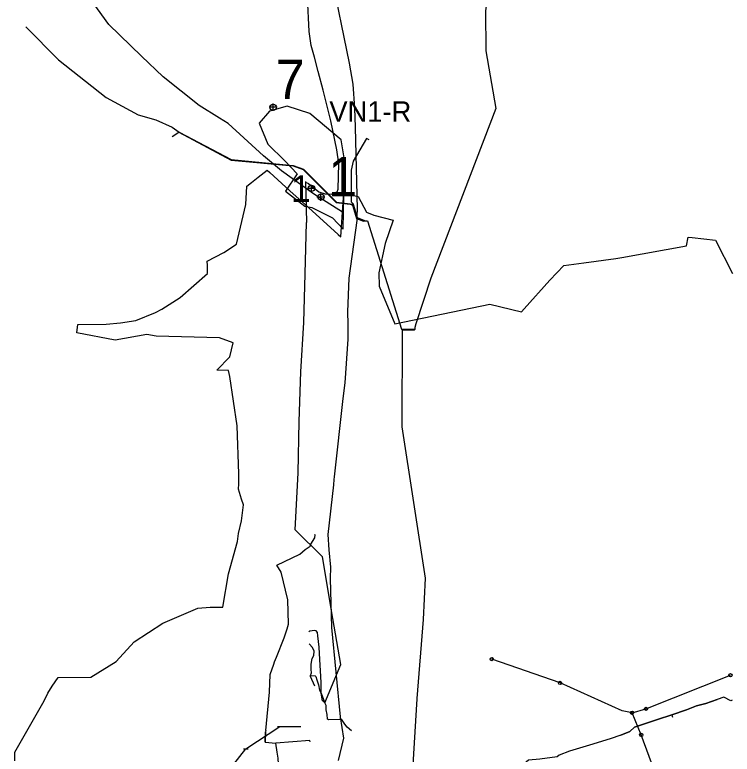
# Model space of a CAD drawing. Extents: x -543464 to -538545, y -1098769 to -1093672.
# Drawn here: x -541444.6 to -540987.8, y -1096571.7 to -1096100.8 of the extents above; entities that cross this region are included whole.
import ezdxf

# ---------------------------------------------------------------- set-up
doc = ezdxf.new("R2010")
doc.units = 0
for name, color, linetype in [('00_CHMI', 7, 'Continuous'), ('00_IGP_sondy', 7, 'Continuous'), ('01_OBVOD PÚ', 7, 'Continuous'), ('03_PC_NAVRH', 7, 'Continuous'), ('05_VHO_V_NÁDRŽ_NAVRH', 7, 'Continuous'), ('07_ELEKTRO', 7, 'Continuous'), ('07_KANALIZACE', 7, 'Continuous'), ('07_SDĚLOVACÍ', 7, 'Continuous'), ('07_VODOVOD', 7, 'Continuous'), ('Default', 7, 'Continuous')]:
    doc.layers.add(name, color=color, linetype=linetype)

# ---------------------------------------------------------------- blocks, each defined once
blk = doc.blocks.new('S_1')
at = {"layer": 'Default'}
blk.add_lwpolyline([(-0.0381, 0), (0.0381, 0)], dxfattribs=at)

msp = doc.modelspace()

# ---------------------------------------------------------------- linework, layer by layer
at = {"layer": '00_CHMI'}
for p, q in [((-541253.22, -1096211.35), (-541258.18, -1096211.35)), ((-541255.66, -1096213.71), (-541255.66, -1096208.99)), ((-541255.66, -1096211.35), (-541255.66, -1096211.35))]:
    msp.add_line(p, q, dxfattribs=at)
msp.add_circle((-541255.66, -1096211.35), 2, dxfattribs=at)
at = {"layer": '00_IGP_sondy'}
for p, q in [((-541277.63, -1096159.69), (-541282.6, -1096159.69)), ((-541280.07, -1096162.05), (-541280.07, -1096157.33)), ((-541280.07, -1096159.69), (-541280.07, -1096159.69)), ((-541247.24, -1096216.9), (-541252.21, -1096216.9)), ((-541249.68, -1096219.26), (-541249.68, -1096214.54)), ((-541249.68, -1096216.9), (-541249.68, -1096216.9))]:
    msp.add_line(p, q, dxfattribs=at)
for centre in [(-541280.07, -1096159.69), (-541249.68, -1096216.9)]:
    msp.add_circle(centre, 2, dxfattribs=at)
at = {"layer": '01_OBVOD PÚ'}
for p, q in [((-541289.55, -1096204.2), (-541283.89, -1096199.82)), ((-541283.89, -1096199.82), (-541282.28, -1096201.28)), ((-541282.28, -1096201.28), (-541269.42, -1096212.92)), ((-541296.92, -1096209.9), (-541293.94, -1096207.59)), ((-541293.94, -1096207.59), (-541289.55, -1096204.2)), ((-541297.39, -1096221.52), (-541296.92, -1096209.9)), ((-541269.42, -1096212.92), (-541257.67, -1096223.56)), ((-541235.2, -1096214.32), (-541225.97, -1096216.6)), ((-541225.97, -1096216.6), (-541220.57, -1096226.59)), ((-541298.38, -1096225.24), (-541297.39, -1096221.52)), ((-541303.33, -1096246.86), (-541298.38, -1096225.24)), ((-541257.67, -1096223.56), (-541238.76, -1096240.68)), ((-541220.57, -1096226.59), (-541215.92, -1096228.43)), ((-541215.92, -1096228.43), (-541203.64, -1096231.56)), ((-541203.64, -1096231.56), (-541208.72, -1096246.41)), ((-541238.76, -1096240.68), (-541237, -1096242.28)), ((-541013.25, -1096242.66), (-540998.52, -1096244.37)), ((-540998.52, -1096244.37), (-540987.61, -1096265.61)), ((-541311.56, -1096252.08), (-541303.33, -1096246.86)), ((-541208.72, -1096246.41), (-541212.87, -1096265.05)), ((-541058.18, -1096255.44), (-541017.03, -1096247.99)), ((-541322.04, -1096257.68), (-541311.56, -1096252.08)), ((-541062.04, -1096255.96), (-541058.18, -1096255.44)), ((-541321.99, -1096260.54), (-541322.04, -1096257.68)), ((-541094.99, -1096260.37), (-541082.29, -1096258.67)), ((-541082.29, -1096258.67), (-541062.04, -1096255.96)), ((-541321.91, -1096265.56), (-541321.99, -1096260.54)), ((-541103.99, -1096269.81), (-541094.99, -1096260.37)), ((-541339.25, -1096280.93), (-541321.91, -1096265.56)), ((-541212.87, -1096265.05), (-541212.56, -1096273.53)), ((-541212.56, -1096273.53), (-541202.58, -1096297.66)), ((-541120.34, -1096288.11), (-541103.99, -1096269.81)), ((-541351.07, -1096288.37), (-541339.25, -1096280.93)), ((-541355.01, -1096290.4), (-541351.07, -1096288.37)), ((-541202.58, -1096297.66), (-541142.15, -1096285.04)), ((-541142.15, -1096285.04), (-541121.99, -1096289.95)), ((-541121.99, -1096289.95), (-541120.34, -1096288.11)), ((-541367.62, -1096295.46), (-541355.01, -1096290.4)), ((-541404.47, -1096298.07), (-541386.31, -1096297.83)), ((-541386.31, -1096297.83), (-541377.38, -1096296.98)), ((-541377.38, -1096296.98), (-541367.62, -1096295.46)), ((-541405.11, -1096303.31), (-541404.47, -1096298.07)), ((-541380.65, -1096308), (-541405.11, -1096303.31)), ((-541360.5, -1096304.33), (-541380.65, -1096308)), ((-541354.52, -1096305.37), (-541360.5, -1096304.33)), ((-541314.25, -1096306.59), (-541354.52, -1096305.37)), ((-541305.58, -1096309.69), (-541314.25, -1096306.59)), ((-541307.59, -1096318.66), (-541305.58, -1096309.69)), ((-541315.99, -1096327.01), (-541307.59, -1096318.66)), ((-541308.6, -1096327.3), (-541315.99, -1096327.01)), ((-541307.75, -1096331.18), (-541308.6, -1096327.3)), ((-541303.06, -1096362.47), (-541307.75, -1096331.18)), ((-541301.91, -1096393.1), (-541303.06, -1096362.47)), ((-541301.88, -1096399.44), (-541301.91, -1096393.1)), ((-541302.11, -1096402.83), (-541301.88, -1096399.44)), ((-541300.19, -1096409.19), (-541302.11, -1096402.83)), ((-541299.07, -1096412.88), (-541300.19, -1096409.19)), ((-541300.19, -1096423.03), (-541299.07, -1096412.88)), ((-541302.26, -1096431.05), (-541300.19, -1096423.03)), ((-541302.73, -1096436.13), (-541302.26, -1096431.05)), ((-541308.44, -1096456.86), (-541302.73, -1096436.13)), ((-541312.11, -1096478.14), (-541308.44, -1096456.86)), ((-541350.23, -1096488.19), (-541328.12, -1096478.71)), ((-541328.12, -1096478.71), (-541320.11, -1096477.98)), ((-541320.11, -1096477.98), (-541312.11, -1096478.14)), ((-541368.51, -1096500.06), (-541350.23, -1096488.19)), ((-541379.97, -1096512.62), (-541368.51, -1096500.06)), ((-541396.15, -1096522.56), (-541379.97, -1096512.62)), ((-541420.77, -1096528.24), (-541417.01, -1096522.78)), ((-541417.01, -1096522.78), (-541396.15, -1096522.56)), ((-541423.44, -1096532.78), (-541420.77, -1096528.24)), ((-541425.82, -1096537.67), (-541423.44, -1096532.78)), ((-541444.58, -1096570.46), (-541425.82, -1096537.67)), ((-541444.58, -1096575.85), (-541444.58, -1096570.46))]:
    msp.add_line(p, q, dxfattribs=at)
for points in [[(-541237, -1096242.28), (-541235.98, -1096226.49), (-541235.2, -1096214.32)], [(-541017.03, -1096247.99), (-541015.98, -1096242.34), (-541013.25, -1096242.66)]]:
    msp.add_lwpolyline(points, dxfattribs=at)
at = {"layer": '03_PC_NAVRH'}
msp.add_lwpolyline([(-541235.98, -1096226.49), (-541254.49, -1096214.81), (-541274.73, -1096200.1), (-541286.23, -1096190.71), (-541308.75, -1096170.04), (-541314.17, -1096166.68), (-541327.14, -1096158.63), (-541350.17, -1096140.39), (-541364, -1096127.2), (-541384.64, -1096107.01), (-541399.17, -1096086.75)], dxfattribs=at)
at = {"layer": '05_VHO_V_NÁDRŽ_NAVRH'}
msp.add_lwpolyline([(-541282.52, -1096162.21), (-541289.06, -1096169.9), (-541283.48, -1096183.26), (-541272.7, -1096193.9), (-541264.78, -1096201.99), (-541272.19, -1096213.11), (-541259.83, -1096222.7), (-541255.57, -1096223.5), (-541242.4, -1096230.17), (-541235.51, -1096237.41), (-541234.65, -1096193.24), (-541236.71, -1096180.51), (-541256.68, -1096163.6), (-541271.18, -1096158.92)], close=True, dxfattribs=at)
at = {"layer": '07_ELEKTRO'}
for points in [[(-541259.6, -1096207.07), (-541259.42, -1096207.48), (-541257.61, -1096208.15), (-541251.01, -1096213.45), (-541247.03, -1096214.79), (-541243.1, -1096215.08), (-541239.32, -1096213.49), (-541238.65, -1096211.86), (-541238.26, -1096195.5), (-541239.52, -1096186.83), (-541243.46, -1096168.28), (-541248.25, -1096148.76), (-541251.5, -1096136.89), (-541253.76, -1096127.88), (-541255.95, -1096120.32), (-541257.09, -1096111.55), (-541258.26, -1096089.5), (-541256.98, -1096076.75), (-541256.19, -1096073.26)], [(-541259.6, -1096207.07), (-541258.92, -1096233.01)], [(-541259.79, -1096265.73), (-541258.92, -1096233.01)], [(-541260.56, -1096296.82), (-541259.79, -1096265.73)], [(-541262.42, -1096328.14), (-541260.56, -1096296.82)], [(-541263.62, -1096359.87), (-541262.42, -1096328.14)], [(-541264.28, -1096392.46), (-541263.62, -1096359.87)], [(-541266.14, -1096428.86), (-541264.28, -1096392.46)], [(-541248.63, -1096445.93), (-541266.14, -1096428.86)], [(-541242.21, -1096485.29), (-541248.63, -1096445.93)], [(-541237.09, -1096514.54), (-541242.21, -1096485.29)], [(-541247.27, -1096539), (-541248.13, -1096538.08), (-541248.74, -1096537.74), (-541249.46, -1096532.71), (-541249.6, -1096526.11), (-541249.86, -1096518.67), (-541250.33, -1096511.36), (-541250.73, -1096503.41), (-541251.67, -1096496.37), (-541251.91, -1096494.16), (-541252.68, -1096493.05), (-541253.74, -1096492.98), (-541256.78, -1096493.41), (-541257.28, -1096493.76)], [(-541256.23, -1096521.6), (-541255.76, -1096519.75), (-541255.91, -1096517.69), (-541255.97, -1096514.28), (-541255.27, -1096510.78), (-541254.1, -1096508.87), (-541254.02, -1096505.98), (-541255.04, -1096503.69), (-541257.2, -1096501.41)], [(-541247.27, -1096539), (-541237.09, -1096514.54)], [(-541256.23, -1096522.09), (-541256.23, -1096521.6)], [(-541256.23, -1096521.6), (-541253.44, -1096521.82), (-541252.97, -1096522.28), (-541252.23, -1096524.3), (-541251.18, -1096527.4), (-541250.56, -1096530.93), (-541249.5, -1096532.73), (-541248.12, -1096536.8), (-541247.27, -1096539)], [(-541253.52, -1096528.29), (-541256.23, -1096522.09)], [(-541230.2, -1096556.88), (-541232.92, -1096554.46), (-541234.47, -1096552.5), (-541236.24, -1096549.98), (-541236.76, -1096549.54), (-541238.14, -1096549.59), (-541244.89, -1096549.8), (-541245.53, -1096549.29), (-541245.74, -1096546.34), (-541246.26, -1096543.52), (-541246.33, -1096540.59), (-541247.27, -1096539)]]:
    msp.add_lwpolyline(points, dxfattribs=at)
at = {"layer": '07_KANALIZACE'}
for p, q in [((-541097.48, -1096526.28), (-541140.98, -1096511.14)), ((-541139.83, -1096510.96), (-541140.69, -1096510.37)), ((-541140.01, -1096511.48), (-541139.83, -1096510.96)), ((-541042.76, -1096542.78), (-540988.95, -1096521.37)), ((-541051.63, -1096545.26), (-541042.76, -1096542.78)), ((-541045.79, -1096559.36), (-541051.63, -1096545.26)), ((-541297.43, -1096568.35), (-541275.76, -1096554.12)), ((-541275.76, -1096554.12), (-541264.02, -1096554.1)), ((-541033.64, -1096592.48), (-541045.79, -1096559.36)), ((-541318.88, -1096595.3), (-541297.43, -1096568.35))]:
    msp.add_line(p, q, dxfattribs=at)
msp.add_lwpolyline([(-541051.63, -1096545.26), (-541058, -1096544.03), (-541097.48, -1096526.28)], dxfattribs=at)
for centre in [(-541140.98, -1096511.14), (-540988.95, -1096521.37), (-541097.48, -1096526.28), (-541042.76, -1096542.78), (-541051.63, -1096545.26), (-541045.79, -1096559.36)]:
    msp.add_circle(centre, 1.03, dxfattribs=at)
at = {"layer": '07_SDĚLOVACÍ'}
for points in [[(-541231.45, -1096131.61), (-541243.12, -1096074.54), (-541244.5, -1096063.59), (-541244.82, -1096060.49), (-541250.59, -1096018.21), (-541251.9, -1096000.62), (-541252.61, -1095980.83), (-541251.5, -1095934.07), (-541250.13, -1095887.69), (-541247.81, -1095854.45)], [(-541227.61, -1096172.28), (-541228.14, -1096160.31), (-541229.24, -1096145.01), (-541231.45, -1096131.61)], [(-541226.57, -1096228.76), (-541226.42, -1096224.51), (-541227.61, -1096172.28)], [(-541241.06, -1096394.94), (-541235.44, -1096345.11), (-541234.22, -1096335.08), (-541232.3, -1096307.35), (-541232.3, -1096297.73), (-541232.48, -1096289.96), (-541231.62, -1096268.45), (-541226.68, -1096231.91), (-541226.57, -1096228.76)], [(-541238.58, -1096575.73), (-541235, -1096561.4), (-541237.2, -1096547.82), (-541242.75, -1096490.95), (-541243.54, -1096459.71), (-541243.39, -1096452.52), (-541244.42, -1096441.55), (-541244.99, -1096431.71), (-541241.5, -1096400.08), (-541241.2, -1096396.64)], [(-541241.2, -1096396.64), (-541241.06, -1096394.94)], [(-541284.76, -1096556.62), (-541282.44, -1096532.11), (-541281.94, -1096520.96), (-541279.71, -1096514.42), (-541279.19, -1096512.91), (-541278.02, -1096509.97), (-541273.09, -1096497.47), (-541271.25, -1096491.92), (-541270.24, -1096488.85), (-541270.83, -1096473.31), (-541274.93, -1096455.7), (-541277.67, -1096451.37), (-541263.15, -1096444.21), (-541259.69, -1096441.34), (-541256.44, -1096439.16), (-541256.17, -1096437.98), (-541253.58, -1096433.89), (-541253.35, -1096432.05), (-541253.68, -1096431.99)], [(-541050.03, -1096554.48), (-541035.32, -1096549.53), (-541026.33, -1096546.63), (-541017.01, -1096543.42), (-541010.65, -1096540.95), (-541004.67, -1096539.4), (-540997.48, -1096536.91)], [(-540988.76, -1096537.73), (-540993.17, -1096535.42), (-540997.48, -1096536.91), (-541004.67, -1096539.4), (-541010.65, -1096540.95), (-541017.01, -1096543.42), (-541026.33, -1096546.63)], [(-540987.77, -1096537.36), (-540988.76, -1096537.73)], [(-541026.33, -1096546.63), (-541035.32, -1096549.53), (-541050.03, -1096554.48), (-541053.05, -1096557.21), (-541058.67, -1096559.45), (-541065.48, -1096561.88), (-541078.69, -1096565.9), (-541091.5, -1096569.67), (-541097.99, -1096572.33), (-541099.29, -1096573.28), (-541110.26, -1096574.8), (-541117.58, -1096575.37), (-541119.98, -1096577.5), (-541121.22, -1096580.58)], [(-541026.33, -1096546.63), (-541026.07, -1096547.42)], [(-541026.07, -1096547.42), (-541025.89, -1096548)], [(-541284.76, -1096556.62), (-541284.99, -1096557.34), (-541285.19, -1096564.02), (-541278.48, -1096564.72)], [(-541285.19, -1096564.02), (-541284.99, -1096557.34)], [(-541058.67, -1096559.45), (-541053.05, -1096557.21)], [(-541256.63, -1096563.82), (-541256.72, -1096562.84), (-541278.48, -1096564.72)], [(-541273.4, -1096590.81), (-541276.17, -1096585.12), (-541276.94, -1096574.27), (-541277.55, -1096570.39), (-541278.48, -1096564.72)]]:
    msp.add_lwpolyline(points, dxfattribs=at)
at = {"layer": '07_VODOVOD'}
for points in [[(-540857.53, -1095605.18), (-540869.92, -1095647.26), (-540945.96, -1095732.03), (-541032.57, -1095842.14), (-541056.67, -1095877.81), (-541075.39, -1095916.83), (-541084.15, -1095933.74), (-541125.19, -1095995.32), (-541132.35, -1096010.24), (-541144.87, -1096098.2), (-541144.65, -1096123.8), (-541138.4, -1096160.38), (-541179.69, -1096268.54), (-541189.35, -1096297.68), (-541189.86, -1096299.98)], [(-541437.65, -1096108.41), (-541416.78, -1096129.42), (-541386.38, -1096153.42), (-541366.1, -1096164.56), (-541354.89, -1096167.76), (-541344.31, -1096172.27), (-541339.94, -1096175.5), (-541306.86, -1096193.06), (-541267.3, -1096196.85), (-541260.86, -1096199.15), (-541239.85, -1096220.14), (-541229.27, -1096221.33), (-541226.75, -1096230.24), (-541222.5, -1096231.75), (-541221.43, -1096232.11)], [(-541344.33, -1096178.25), (-541340.05, -1096175.66), (-541306.85, -1096193.42), (-541267.34, -1096197.05), (-541260.96, -1096199.34), (-541239.93, -1096220.33), (-541229.42, -1096221.52), (-541226.93, -1096230.43), (-541222.6, -1096232.05), (-541221.43, -1096232.11)], [(-541219.06, -1096180.34), (-541220.62, -1096179.68), (-541229.25, -1096194.07), (-541230.48, -1096199.82), (-541230.33, -1096219.99), (-541229.11, -1096221.2), (-541228.88, -1096221.96), (-541226.52, -1096229.98), (-541222.44, -1096231.56), (-541221.43, -1096232.11)], [(-541230.16, -1096221.79), (-541229.53, -1096222.08), (-541227.09, -1096230.61), (-541222.63, -1096232.24), (-541221.43, -1096232.11)], [(-541221.43, -1096232.11), (-541220.48, -1096232.09), (-541219.96, -1096232.08), (-541198.33, -1096301.03), (-541190.35, -1096300.95), (-541189.86, -1096301.12)], [(-541188.33, -1096536.25), (-541184.38, -1096485.94), (-541183.15, -1096459.58), (-541197.87, -1096363.18), (-541197.73, -1096301.69), (-541190.2, -1096301.36), (-541189.86, -1096301.12)], [(-541189.86, -1096299.98), (-541189.81, -1096300.94), (-541189.86, -1096301.12)], [(-541190.4, -1096647.55), (-541189.31, -1096641.43), (-541191.41, -1096585.37), (-541188.37, -1096536.46), (-541188.33, -1096536.25)], [(-541188.65, -1096536.22), (-541188.46, -1096536.22), (-541188.33, -1096536.25)]]:
    msp.add_lwpolyline(points, dxfattribs=at)

# ---------------------------------------------------------------- block references
at = {"layer": '07_KANALIZACE', "xscale": 39.3602801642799, "yscale": 39.36028016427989, "rotation": -0.010678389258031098}
for p in [(-541275.76, -1096554.12), (-541264.02, -1096554.1), (-541297.43, -1096568.35)]:
    msp.add_blockref('S_1', p, dxfattribs=at)

# ---------------------------------------------------------------- texts
at = {"layer": '00_CHMI'}
msp.add_text('1', height=17, dxfattribs=at).set_placement((-541268.72, -1096219.97))
at = {"layer": '00_IGP_sondy'}
for s, p in [('7', (-541278.6, -1096154.46)), ('1', (-541245.08, -1096216.36))]:
    msp.add_text(s, height=25, dxfattribs=at).set_placement(p)
at = {"layer": '05_VHO_V_NÁDRŽ_NAVRH'}
msp.add_text('VN1-R', height=13, dxfattribs=at).set_placement((-541244.31, -1096168.9))

doc.saveas('drawing.dxf')
